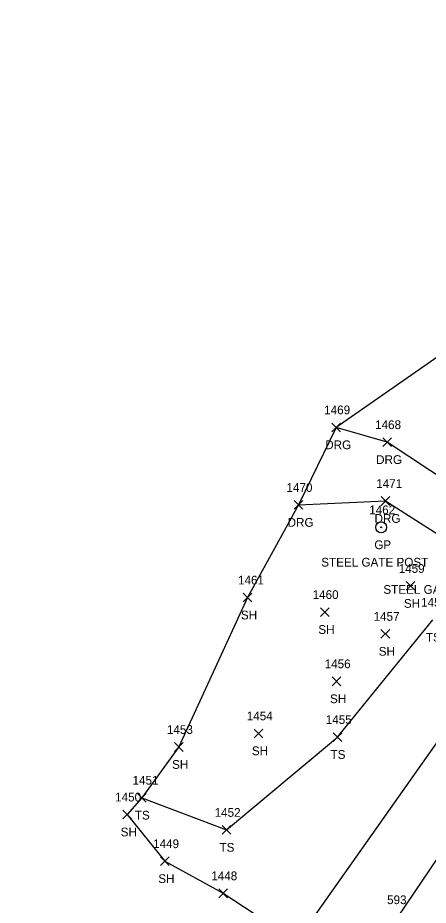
# Model space of a CAD drawing. Extents: x 1639430 to 1640195, y 612006 to 612917.
# Drawn here: x 1639571.6 to 1639665.7, y 612311.8 to 612515.2 of the extents above; entities that cross this region are included whole.
import ezdxf

# ---------------------------------------------------------------- set-up
doc = ezdxf.new("R2010")
doc.units = 0
for name, color, linetype in [('L_A', 7, 'Continuous'), ('L_I', 7, 'Continuous'), ('L_TIC', 7, 'Continuous'), ('LELB', 7, 'Continuous'), ('LSOGP', 7, 'Continuous'), ('P_I', 7, 'Continuous'), ('PET', 7, 'Continuous'), ('PRC', 7, 'Continuous'), ('R_A', 7, 'Continuous'), ('R_C', 7, 'Continuous'), ('R_I', 7, 'Continuous'), ('R_TIC', 7, 'Continuous'), ('RDG', 7, 'Continuous'), ('RGP', 7, 'Continuous')]:
    doc.layers.add(name, color=color, linetype=linetype)

msp = doc.modelspace()

# ---------------------------------------------------------------- linework, layer by layer
at = {"layer": 'L_TIC'}
for points in [[(1639660.59, 612383.96), (1639662.59, 612385.96)], [(1639662.59, 612383.96), (1639660.59, 612385.96)], [(1639623.25, 612381.3), (1639625.25, 612383.3)], [(1639625.25, 612381.3), (1639623.25, 612383.3)], [(1639640.99, 612377.98), (1639642.99, 612379.98)], [(1639642.99, 612377.98), (1639640.99, 612379.98)], [(1639654.83, 612372.98), (1639656.83, 612374.98)], [(1639656.83, 612372.98), (1639654.83, 612374.98)], [(1639643.67, 612362.11), (1639645.67, 612364.11)], [(1639645.67, 612362.11), (1639643.67, 612364.11)], [(1639625.77, 612350.18), (1639627.77, 612352.18)], [(1639627.77, 612350.18), (1639625.77, 612352.18)], [(1639643.87, 612349.34), (1639645.87, 612351.34)], [(1639645.87, 612349.34), (1639643.87, 612351.34)], [(1639607.49, 612347.06), (1639609.49, 612349.06)], [(1639609.49, 612347.06), (1639607.49, 612349.06)], [(1639599.03, 612335.44), (1639601.03, 612337.44)], [(1639601.03, 612335.44), (1639599.03, 612337.44)], [(1639595.7, 612331.58), (1639597.7, 612333.58)], [(1639597.7, 612331.58), (1639595.7, 612333.58)], [(1639618.42, 612328.06), (1639620.42, 612330.06)], [(1639620.42, 612328.06), (1639618.42, 612330.06)], [(1639604.32, 612320.89), (1639606.32, 612322.89)], [(1639606.32, 612320.89), (1639604.32, 612322.89)], [(1639617.65, 612313.53), (1639619.65, 612315.53)], [(1639619.65, 612313.53), (1639617.65, 612315.53)]]:
    msp.add_lwpolyline(points, dxfattribs=at)
at = {"layer": 'LELB'}
msp.add_lwpolyline([(1639600.03, 612336.44), (1639619.42, 612329.06), (1639644.87, 612350.34), (1639666.72, 612377.2)], dxfattribs=at)
at = {"layer": 'LSOGP'}
msp.add_lwpolyline([(1639717.74, 612525.52), (1639714.82, 612520.27), (1639697.1, 612487.64), (1639680.04, 612445.97), (1639644.57, 612421.3), (1639635.96, 612403.52), (1639624.25, 612382.3), (1639608.49, 612348.06), (1639600.03, 612336.44), (1639596.7, 612332.58), (1639605.32, 612321.89), (1639618.65, 612314.53), (1639630.7, 612306.67)], dxfattribs=at)
at = {"layer": 'PET'}
msp.add_lwpolyline([(1639571.61, 612204.8), (1639581.27, 612221.94), (1639610.12, 612263.74), (1639636.18, 612301.91), (1639636.72, 612305.17), (1639674.04, 612358.08), (1639681.53, 612370.21), (1639706.2, 612406.33), (1639726.2, 612437.98), (1639749.36, 612475.33)], dxfattribs=at)
at = {"layer": 'PRC'}
msp.add_lwpolyline([(1639744.51, 612441.45), (1639719.17, 612400.96), (1639690.59, 612356.39), (1639658.59, 612309.05), (1639630.32, 612267.52), (1639611.01, 612239.3), (1639581.06, 612195.34)], dxfattribs=at)
at = {"layer": 'R_TIC'}
for points in [[(1639643.57, 612420.3), (1639645.57, 612422.3)], [(1639645.57, 612420.3), (1639643.57, 612422.3)], [(1639655.23, 612416.91), (1639657.23, 612418.91)], [(1639657.23, 612416.91), (1639655.23, 612418.91)], [(1639634.96, 612402.52), (1639636.96, 612404.52)], [(1639636.96, 612402.52), (1639634.96, 612404.52)], [(1639654.88, 612403.43), (1639656.88, 612405.43)], [(1639656.88, 612403.43), (1639654.88, 612405.43)]]:
    msp.add_lwpolyline(points, dxfattribs=at)
at = {"layer": 'RDG'}
for points in [[(1639686.41, 612401.12), (1639676.14, 612404.74), (1639656.23, 612417.91), (1639644.57, 612421.3)], [(1639635.96, 612403.52), (1639655.88, 612404.43), (1639672.32, 612394.03), (1639677.47, 612389.95)]]:
    msp.add_lwpolyline(points, dxfattribs=at)
at = {"layer": 'RGP'}
msp.add_line((1639654.88, 612398.4), (1639654.88, 612398.4), dxfattribs=at)
for radius in [1.25, 0.0833]:
    msp.add_circle((1639654.88, 612398.4), radius, dxfattribs=at)

# ---------------------------------------------------------------- texts
at = {"layer": 'L_A'}
for s, p in [('SH', (1639660.08, 612379.96)), ('SH', (1639622.74, 612377.3)), ('SH', (1639640.48, 612373.98)), ('TS', (1639665.13, 612372.2)), ('SH', (1639654.32, 612368.98)), ('SH', (1639643.16, 612358.11)), ('SH', (1639625.25, 612346.18)), ('TS', (1639643.28, 612345.34)), ('SH', (1639606.97, 612343.06)), ('TS', (1639598.44, 612331.44)), ('SH', (1639595.19, 612327.58)), ('TS', (1639617.83, 612324.06)), ('SH', (1639603.81, 612316.89))]:
    msp.add_text(s, height=2, dxfattribs=at).set_placement(p)
at = {"layer": 'L_I'}
for s, p in [('1459', (1639658.89, 612387.96)), ('1461', (1639622.08, 612385.3)), ('1460', (1639639.17, 612381.98)), ('1458', (1639664.03, 612380.2)), ('1457', (1639653.14, 612376.98)), ('1456', (1639641.93, 612366.11)), ('1454', (1639624.07, 612354.18)), ('1455', (1639642.18, 612353.34)), ('1453', (1639605.79, 612351.06)), ('1451', (1639597.91, 612339.44)), ('1450', (1639593.92, 612335.58)), ('1452', (1639616.72, 612332.06)), ('1449', (1639602.62, 612324.89)), ('1448', (1639615.95, 612317.53))]:
    msp.add_text(s, height=2, dxfattribs=at).set_placement(p)
at = {"layer": 'P_I'}
msp.add_text('593', height=2, dxfattribs=at).set_placement((1639656.23, 612312.05))
at = {"layer": 'R_A'}
for s, p in [('DRG', (1639642.06, 612416.3)), ('DRG', (1639653.72, 612412.91)), ('DRG', (1639633.44, 612398.52)), ('DRG', (1639653.36, 612399.43)), ('GP', (1639653.31, 612393.4))]:
    msp.add_text(s, height=2, dxfattribs=at).set_placement(p)
at = {"layer": 'R_C'}
for p in [(1639641.15, 612389.4), (1639655.38, 612383.16)]:
    msp.add_text('STEEL GATE POST', height=2, dxfattribs=at).set_placement(p)
at = {"layer": 'R_I'}
for s, p in [('1469', (1639641.82, 612424.3)), ('1468', (1639653.49, 612420.91)), ('1470', (1639633.18, 612406.52)), ('1471', (1639653.75, 612407.43)), ('1462', (1639652.14, 612401.4))]:
    msp.add_text(s, height=2, dxfattribs=at).set_placement(p)

doc.saveas('drawing.dxf')
